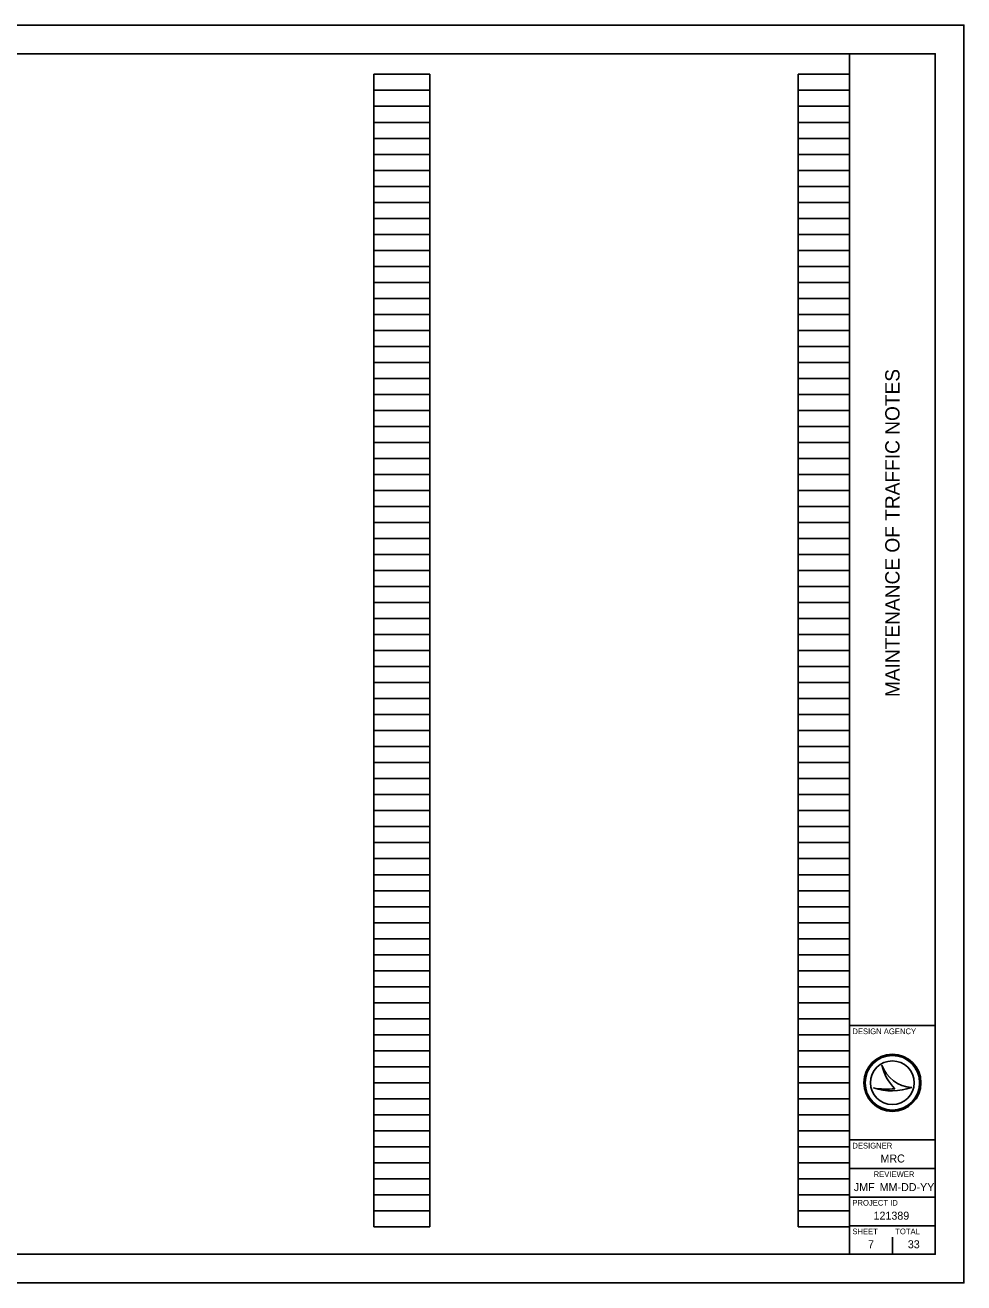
# Model space of a CAD drawing. Extents: x 0 to 34, y 0 to 22.
# Drawn here: x 17.58 to 34, y 0 to 22 of the extents above; entities that cross this region are included whole.
import ezdxf

# ---------------------------------------------------------------- set-up
doc = ezdxf.new("R2010")
doc.units = 0
for name, color, linetype in [('SH_Border', 7, 'Continuous'), ('SH_Cut_Line', 7, 'Continuous'), ('SH_Data', 7, 'Continuous')]:
    doc.layers.add(name, color=color, linetype=linetype)

msp = doc.modelspace()

# ---------------------------------------------------------------- linework, layer by layer
at = {"layer": 'SH_Border'}
for p, q in [((32, 0.5), (32, 21.5)), ((32, 4.5), (33.5, 4.5)), ((32, 2.5), (33.5, 2.5)), ((32, 2), (33.5, 2)), ((32, 1.5), (33.5, 1.5)), ((32, 1), (33.5, 1))]:
    msp.add_line(p, q, dxfattribs=at)
msp.add_lwpolyline([(1.5, 21.5), (33.5, 21.5), (33.5, 0.5), (1.5, 0.5)], close=True, dxfattribs=at)
at = {"layer": 'SH_Cut_Line'}
msp.add_lwpolyline([(0, 0), (34, 0), (34, 22), (0, 22)], close=True, dxfattribs=at)
at = {"layer": 'SH_Data'}
for p, q in [((23.68, 0.98), (23.68, 21.14)), ((23.68, 21.14), (24.66, 21.14)), ((24.66, 0.98), (24.66, 21.14)), ((31.1, 0.98), (31.1, 21.14)), ((31.1, 21.14), (32, 21.14)), ((32, 0.98), (32, 21.14)), ((23.68, 20.86), (24.66, 20.86)), ((31.1, 20.86), (32, 20.86)), ((23.68, 20.58), (24.66, 20.58)), ((31.1, 20.58), (32, 20.58)), ((23.68, 20.3), (24.66, 20.3)), ((31.1, 20.3), (32, 20.3)), ((23.68, 20.02), (24.66, 20.02)), ((31.1, 20.02), (32, 20.02)), ((23.68, 19.74), (24.66, 19.74)), ((31.1, 19.74), (32, 19.74)), ((23.68, 19.46), (24.66, 19.46)), ((31.1, 19.46), (32, 19.46)), ((23.68, 19.18), (24.66, 19.18)), ((31.1, 19.18), (32, 19.18)), ((23.68, 18.9), (24.66, 18.9)), ((31.1, 18.9), (32, 18.9)), ((23.68, 18.62), (24.66, 18.62)), ((31.1, 18.62), (32, 18.62)), ((23.68, 18.34), (24.66, 18.34)), ((31.1, 18.34), (32, 18.34)), ((23.68, 18.06), (24.66, 18.06)), ((31.1, 18.06), (32, 18.06)), ((23.68, 17.78), (24.66, 17.78)), ((31.1, 17.78), (32, 17.78)), ((23.68, 17.5), (24.66, 17.5)), ((31.1, 17.5), (32, 17.5)), ((23.68, 17.22), (24.66, 17.22)), ((31.1, 17.22), (32, 17.22)), ((23.68, 16.94), (24.66, 16.94)), ((31.1, 16.94), (32, 16.94)), ((23.68, 16.66), (24.66, 16.66)), ((31.1, 16.66), (32, 16.66)), ((23.68, 16.38), (24.66, 16.38)), ((31.1, 16.38), (32, 16.38)), ((23.68, 16.1), (24.66, 16.1)), ((31.1, 16.1), (32, 16.1)), ((23.68, 15.82), (24.66, 15.82)), ((31.1, 15.82), (32, 15.82)), ((23.68, 15.54), (24.66, 15.54)), ((31.1, 15.54), (32, 15.54)), ((23.68, 15.26), (24.66, 15.26)), ((31.1, 15.26), (32, 15.26)), ((23.68, 14.98), (24.66, 14.98)), ((31.1, 14.98), (32, 14.98)), ((23.68, 14.7), (24.66, 14.7)), ((31.1, 14.7), (32, 14.7)), ((23.68, 14.42), (24.66, 14.42)), ((31.1, 14.42), (32, 14.42)), ((23.68, 14.14), (24.66, 14.14)), ((31.1, 14.14), (32, 14.14)), ((23.68, 13.86), (24.66, 13.86)), ((31.1, 13.86), (32, 13.86)), ((23.68, 13.58), (24.66, 13.58)), ((31.1, 13.58), (32, 13.58)), ((23.68, 13.3), (24.66, 13.3)), ((31.1, 13.3), (32, 13.3)), ((23.68, 13.02), (24.66, 13.02)), ((31.1, 13.02), (32, 13.02)), ((23.68, 12.74), (24.66, 12.74)), ((31.1, 12.74), (32, 12.74)), ((23.68, 12.46), (24.66, 12.46)), ((31.1, 12.46), (32, 12.46)), ((23.68, 12.18), (24.66, 12.18)), ((31.1, 12.18), (32, 12.18)), ((23.68, 11.9), (24.66, 11.9)), ((31.1, 11.9), (32, 11.9)), ((23.68, 11.62), (24.66, 11.62)), ((31.1, 11.62), (32, 11.62)), ((23.68, 11.34), (24.66, 11.34)), ((31.1, 11.34), (32, 11.34)), ((23.68, 11.06), (24.66, 11.06)), ((31.1, 11.06), (32, 11.06)), ((23.68, 10.78), (24.66, 10.78)), ((31.1, 10.78), (32, 10.78)), ((23.68, 10.5), (24.66, 10.5)), ((31.1, 10.5), (32, 10.5)), ((23.68, 10.22), (24.66, 10.22)), ((31.1, 10.22), (32, 10.22)), ((23.68, 9.94), (24.66, 9.94)), ((31.1, 9.94), (32, 9.94)), ((23.68, 9.66), (24.66, 9.66)), ((31.1, 9.66), (32, 9.66)), ((23.68, 9.38), (24.66, 9.38)), ((31.1, 9.38), (32, 9.38)), ((23.68, 9.1), (24.66, 9.1)), ((31.1, 9.1), (32, 9.1)), ((23.68, 8.82), (24.66, 8.82)), ((31.1, 8.82), (32, 8.82)), ((23.68, 8.54), (24.66, 8.54)), ((31.1, 8.54), (32, 8.54)), ((23.68, 8.26), (24.66, 8.26)), ((31.1, 8.26), (32, 8.26)), ((23.68, 7.98), (24.66, 7.98)), ((31.1, 7.98), (32, 7.98)), ((23.68, 7.7), (24.66, 7.7)), ((31.1, 7.7), (32, 7.7)), ((23.68, 7.42), (24.66, 7.42)), ((31.1, 7.42), (32, 7.42)), ((23.68, 7.14), (24.66, 7.14)), ((31.1, 7.14), (32, 7.14)), ((23.68, 6.86), (24.66, 6.86)), ((31.1, 6.86), (32, 6.86)), ((23.68, 6.58), (24.66, 6.58)), ((31.1, 6.58), (32, 6.58)), ((23.68, 6.3), (24.66, 6.3)), ((31.1, 6.3), (32, 6.3)), ((23.68, 6.02), (24.66, 6.02)), ((31.1, 6.02), (32, 6.02)), ((23.68, 5.74), (24.66, 5.74)), ((31.1, 5.74), (32, 5.74)), ((23.68, 5.46), (24.66, 5.46)), ((31.1, 5.46), (32, 5.46)), ((23.68, 5.18), (24.66, 5.18)), ((31.1, 5.18), (32, 5.18)), ((23.68, 4.9), (24.66, 4.9)), ((31.1, 4.9), (32, 4.9)), ((23.68, 4.62), (24.66, 4.62)), ((31.1, 4.62), (32, 4.62)), ((23.68, 4.34), (24.66, 4.34)), ((31.1, 4.34), (32, 4.34)), ((23.68, 4.06), (24.66, 4.06)), ((31.1, 4.06), (32, 4.06)), ((23.68, 3.78), (24.66, 3.78)), ((31.1, 3.78), (32, 3.78)), ((32.567, 3.81), (32.567, 3.81)), ((23.68, 3.5), (24.66, 3.5)), ((31.1, 3.5), (32, 3.5)), ((32.417, 3.41), (32.417, 3.41)), ((32.75, 3.5), (32.75, 3.5)), ((33.087, 3.419), (33.087, 3.419)), ((23.68, 3.22), (24.66, 3.22)), ((31.1, 3.22), (32, 3.22)), ((23.68, 2.94), (24.66, 2.94)), ((31.1, 2.94), (32, 2.94)), ((23.68, 2.66), (24.66, 2.66)), ((31.1, 2.66), (32, 2.66)), ((23.68, 2.38), (24.66, 2.38)), ((31.1, 2.38), (32, 2.38)), ((23.68, 2.1), (24.66, 2.1)), ((31.1, 2.1), (32, 2.1)), ((23.68, 1.82), (24.66, 1.82)), ((31.1, 1.82), (32, 1.82)), ((23.68, 1.54), (24.66, 1.54)), ((31.1, 1.54), (32, 1.54)), ((23.68, 1.26), (24.66, 1.26)), ((31.1, 1.26), (32, 1.26)), ((23.68, 0.98), (24.66, 0.98)), ((31.1, 0.98), (32, 0.98)), ((32.375, 0.675), (32.375, 0.675)), ((32.75, 0.5), (32.75, 0.8))]:
    msp.add_line(p, q, dxfattribs=at)
for radius in [0.5, 0.477, 0.477, 0.382]:
    msp.add_circle((32.75, 3.5), radius, dxfattribs=at)
for centre, radius, start, end in [((33.116, 3.998), 0.58, 198.9257, 198.9319), ((33.347, 3.97), 0.796, 191.6379, 191.6421), ((33.116, 3.998), 0.58, 198.9319, 267.1657), ((33.347, 3.97), 0.796, 191.6421, 226.0947), ((32.739, 4.37), 1.013, 251.4576, 290.0832), ((32.648, 4.654), 1.266, 259.4964, 259.4995), ((32.739, 4.37), 1.013, 251.4527, 251.4576), ((32.648, 4.654), 1.266, 259.4995, 276.6672)]:
    msp.add_arc(centre, radius, start, end, dxfattribs=at)

# ---------------------------------------------------------------- texts
msp.add_text('MAINTENANCE OF TRAFFIC NOTES', height=0.25, rotation=90, dxfattribs=at).set_placement((32.875, 10.247))
for s, height, p in [('DESIGN AGENCY', 0.1, (32.05, 4.35)), ('DESIGNER', 0.1, (32.05, 2.35)), ('MRC', 0.14, (32.541, 2.105)), ('REVIEWER', 0.1, (32.422, 1.85)), ('JMF', 0.14, (32.075, 1.605)), ('MM-DD-YY', 0.14, (32.527, 1.605)), ('PROJECT ID', 0.1, (32.05, 1.35)), ('121389', 0.14, (32.42, 1.105)), ('SHEET', 0.1, (32.05, 0.85)), ('TOTAL', 0.1, (32.8, 0.85)), ('7', 0.14, (32.324, 0.605)), ('33', 0.14, (33.02, 0.605))]:
    msp.add_text(s, height=height, dxfattribs=at).set_placement(p)

doc.saveas('drawing.dxf')
